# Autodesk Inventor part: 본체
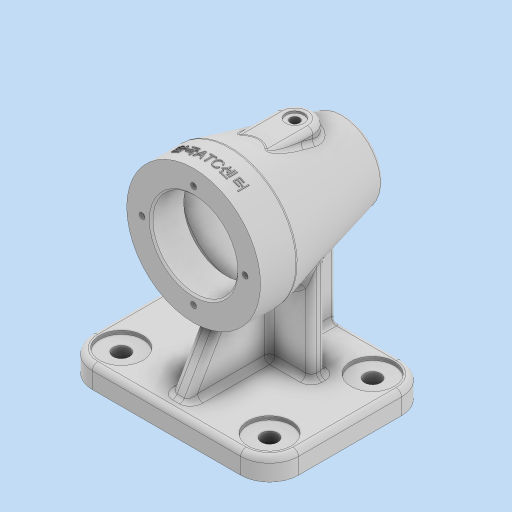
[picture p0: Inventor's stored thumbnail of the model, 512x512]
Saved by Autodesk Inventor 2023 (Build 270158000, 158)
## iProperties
Created: 2024-12
Part Number: 본체
Material: 일반
Document SubType Name: Modeling
Designer: asung
Density: 1 g/cm^3
Appearance: 기본값
Author: asung
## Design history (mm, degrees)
sketch "스케치1"
  geometry: L1 (41, -44.5)-(-41, -44.5); L2 (-57, -28.5)-(-57, 28.5); L3 (-41, 44.5)-(41, 44.5); L4 (57, 28.5)-(57, -28.5); L5 (57, -44.5)-(-57, 44.5); L6 (-57, -44.5)-(57, 44.5); A1 r 16 centre (41, -28.5) between (41, -44.5) and (57, -28.5); A2 r 16 centre (41, 28.5) between (57, 28.5) and (41, 44.5); A3 r 16 centre (-41, 28.5) between (-41, 44.5) and (-57, 28.5); A4 r 16 centre (-41, -28.5) between (-57, -28.5) and (-41, -44.5); 1 further point
  constraints: 12 end point, 8 point on circle, 8 point on line, 8 tangent, 4 centre point, 3 equal radius, 2 midpoint, 2 parallel, 1 horizontal, 1 perpendicular
  dimensions: "d0" = 114 distance of L5.end L6.end; "d1" = 89 distance of L6.start L5.end; "d2" = 16 radius of A1
extrude "돌출1" new body sketch "스케치1" distance "d3" = 12; taper "d4" = 0 deg
fillet "모깎기1" dims "d5" = 3
sketch "스케치2"
  geometry: A1 r 16 centre (-41, 28.5) between (-41, 44.5) and (-57, 28.5) reference; A2 r 16 centre (41, 28.5) between (57, 28.5) and (41, 44.5) reference; A3 r 16 centre (-41, -28.5) between (-57, -28.5) and (-41, -44.5) reference; A4 r 16 centre (41, -28.5) between (41, -44.5) and (57, -28.5) reference; 5 further points
  constraints: 4 coincident
hole "구멍1" sketch "스케치2" at (-41, 28.5), (41, 28.5), (-41, -28.5), (41, -28.5) diameter "d6" = 9; stored, may be unused: countersink angle "d10" = 90 deg, drill point angle "d12" = 0 deg; dims "d7" = 6, "d8" = 24, "d9" = 2, "d11" = 12
node "작업 평면1"
sketch "스케치3"
  geometry: L1 (9, -44.5)-(0, -44.5) reference; L2 (0, -44.5)-(0, 44.5) reference; L3 (0, 44.5)-(9, 44.5) reference; L4 (12, 41.5)-(12, -41.5) reference; L5 (9, -44.5)-(0, -44.5) reference; L6 (0, -44.5)-(0, 44.5) reference; L7 (0, 44.5)-(9, 44.5) reference; L8 (12, 41.5)-(12, -41.5) reference; L9 (9, -44.5)-(0, -44.5) reference; L10 (0, -44.5)-(0, 44.5) reference; L11 (0, 44.5)-(9, 44.5) reference; L12 (12, 41.5)-(12, -41.5) reference; L13 (0, 44.5)-(82, 44.5); L14 (82, 44.5)-(82, 29.5); L15 (82, 29.5)-(82, -54.5); L16 (119, 29.5)-(45, 29.5); L17 (103, -54.5)-(61, -54.5); L18 (119, 29.5)-(119, 9.5); L19 (119, 9.5)-(103, -54.5); A1 r 3 centre (9, -41.5) between (9, -44.5) and (12, -41.5) reference; A2 r 3 centre (9, 41.5) between (12, 41.5) and (9, 44.5) reference; A3 r 3 centre (9, -41.5) between (9, -44.5) and (12, -41.5) reference; A4 r 3 centre (9, 41.5) between (12, 41.5) and (9, 44.5) reference; A5 r 3 centre (9, -41.5) between (9, -44.5) and (12, -41.5) reference; A6 r 3 centre (9, 41.5) between (12, 41.5) and (9, 44.5) reference; 1 further point
  constraints: 14 end point, 3 horizontal, 2 midpoint, 2 vertical, 1 perpendicular
  dimensions: "d14" = 82 distance of L2.end L13.end; "d15" = 15 distance of L14.end L13.end; "d16" = 84 distance of L14.end L15.end; "d17" = 74 distance of L16.start L16.end; "d18" = 42 distance of L17.start L17.end; "d19" = 20 distance of L16.start L18.end
revolve "회전1" sketch "스케치3" stored, may be unused: angle "d20" = 90 deg
fillet "모깎기2" dims "d21" = 3
sketch "스케치4"
  geometry: L1 through (9, -44.5) direction (-1, 0) reference; L2 through (0, 44.5) direction (1, 9.87e-16) reference; L3 through (12, 41.5) direction (0, -1) reference; L4 through (100.658, -54.5) direction (-1, 0) reference; L5 through (60.432, -52.228) direction (-0.243, 0.97) reference; L6 through (45, 9.869) direction (0, 1) reference; L7 through (119, 29.5) direction (0, -1) reference; L8 through (9, -44.5) direction (-1, 0) reference; L9 through (0, 44.5) direction (1, 9.87e-16) reference; L10 through (12, 41.5) direction (0, -1) reference; L11 through (118.91, 9.142) direction (-0.243, -0.97) reference; L12 through (100.658, -54.5) direction (-1, 0) reference; L13 through (60.432, -52.228) direction (-0.243, 0.97) reference; L14 through (45, 9.869) direction (0, 1) reference; L15 through (45, 29.5) direction (1, 2.4e-16) reference; L16 through (119, 29.5) direction (0, -1) reference; L17 through (9, -44.5) direction (-1, 0) reference; L18 through (0, 44.5) direction (1, 9.87e-16) reference; L19 through (12, 41.5) direction (0, -1) reference; L20 through (118.91, 9.142) direction (-0.243, -0.97) reference; L21 through (100.658, -54.5) direction (-1, 0) reference; L22 through (60.432, -52.228) direction (-0.243, 0.97) reference; L23 through (45, 9.869) direction (0, 1) reference; L24 through (45, 29.5) direction (1, 2.4e-16) reference; L25 through (119, 29.5) direction (0, -1) reference; L26 through (9, -44.5) direction (-1, 0) reference; L27 through (0, 44.5) direction (1, 9.87e-16) reference; L28 through (12, 41.5) direction (0, -1) reference; L29 through (118.91, 9.142) direction (-0.243, -0.97) reference; L30 through (100.658, -54.5) direction (-1, 0) reference; L31 through (60.432, -52.228) direction (-0.243, 0.97) reference; L32 through (45, 9.869) direction (0, 1) reference; L33 through (45, 29.5) direction (1, 2.4e-16) reference; L34 through (119, 29.5) direction (0, -1) reference; L35 through (9, -44.5) direction (-1, 0) reference; L36 through (0, 44.5) direction (1, 9.87e-16) reference; L37 through (12, 41.5) direction (0, -1) reference; L38 through (118.91, 9.142) direction (-0.243, -0.97) reference; L39 through (100.658, -54.5) direction (-1, 0) reference; L40 through (60.432, -52.228) direction (-0.243, 0.97) reference; L41 through (45, 9.869) direction (0, 1) reference; L42 through (45, 29.5) direction (1, 2.4e-16) reference; L43 through (119, 29.5) direction (0, -1) reference; L44 through (9, -44.5) direction (-1, 0) reference; L45 through (0, 44.5) direction (1, 9.87e-16) reference; L46 through (12, 41.5) direction (0, -1) reference; L47 through (118.91, 9.142) direction (-0.243, -0.97) reference; L48 through (60.432, -52.228) direction (-0.243, 0.97) reference; L49 through (45, 9.869) direction (0, 1) reference; L50 through (45, 29.5) direction (1, 2.4e-16) reference; L51 (82, 29.5)-(82, -54.5); L52 (105.5, 29.5)-(105.5, 11.5); L53 (105.5, 11.5)-(107.942, 11.5); L54 (112.793, 5.287)-(103.664, -31.228); L55 (100.754, -33.5)-(99.5, -33.5); L56 (99.5, -33.5)-(99.5, -43.2); L57 (99.2, -43.5)-(97.5, -43.5); L58 (95.914, -43.5)-(95.914, -43.5); L59 (94.5, -46.5)-(82, -46.5); L60 (97.5, -43.5)-(97.5, -43.5); L61 through (9, -44.5) direction (-1, 0) reference; L62 through (0, 44.5) direction (1, 9.87e-16) reference; L63 through (12, 41.5) direction (0, -1) reference; L64 through (118.91, 9.142) direction (-0.243, -0.97) reference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; A1 r 5 centre (107.942, 6.5) between (112.793, 5.287) and (107.942, 11.5); A2 r 3 centre (100.754, -30.5) between (100.754, -33.5) and (103.664, -31.228); A3 r 0.3 centre (99.2, -43.2) between (99.2, -43.5) and (99.5, -43.2); A4 r 3 centre (94.5, -43.5) between (94.5, -46.5) and (97.5, -43.5); 83 further points; 32 other entities
  constraints: 20 end point, 9 point on line, 8 horizontal alignment, 8 point on circle, 8 tangent, 6 perpendicular, 4 centre point, 1 horizontal, 1 vertical, 121 other
  dimensions: "d22" = 5 dimension on L54; "d23" = 47 diameter of L52 L51; "d24" = 18 dimension on L53; "d25" = 45 vertical distance of point (114.346, 11.5) point (103.096, -33.5); "d26" = 10 distance of L55.end point (99.5, -43.5); "d28" = 5 radius of A1; "d29" = 3 radius of A2; "d30" = 0.3 radius of A3; "d31" = 35 diameter of L56 L51; "d33" = 31 diameter of L60 L51; "d34" = 3 distance between parallel lines of L57 L59; "d35" = 3 radius of A4 (derived)
  node "절단 모서리 투영4"
  node "절단 모서리 투영5"
  node "절단 모서리 투영6"
  node "절단 모서리 투영7"
  node "절단 모서리 투영8"
  node "절단 모서리 투영9"
  node "절단 모서리 투영10"
  node "절단 모서리 투영11"
  node "절단 모서리 투영12"
  node "절단 모서리 투영13"
  node "절단 모서리 투영14"
  node "절단 모서리 투영15"
  node "절단 모서리 투영16"
revolve "회전2" stored, may be unused: angle "d37" = 90 deg
chamfer "모따기1" distance "d38" = 1; stored, may be unused: second distance "d39" = 2, angle "d40" = 45 deg
chamfer "모따기2" distance "d41" = 1; stored, may be unused: second distance "d42" = 2, angle "d43" = 45 deg
node "작업 평면2"
sketch "스케치5"
  geometry: L1 (24.5, 29.5)-(-24.5, 29.5) reference; L2 (0, 29.5)-(0, -26.5); L3 (10, 29.5)-(10, -26.5); L4 (-10, 29.5)-(-10, -26.5); L5 (-16.733, 9.869)-(-16.733, 29.5) reference; L6 (-16.733, 29.5)-(16.733, 29.5) reference; L7 (16.733, 29.5)-(16.733, 9.869) reference; L8 (-10, 29.5)-(10, 29.5); L9 (-16.733, 9.869)-(-16.733, 29.5) reference; L10 (-16.733, 29.5)-(16.733, 29.5) reference; L11 (16.733, 29.5)-(16.733, 9.869) reference; L12 (-16.733, 9.869)-(-16.733, 29.5) reference; L13 (-16.733, 29.5)-(16.733, 29.5) reference; L14 (16.733, 29.5)-(16.733, 9.869) reference; L15 (-21.568, -52.228)-(21.568, -52.228) reference; L16 (36.91, 9.142)-(-36.91, 9.142) reference; L17 (30.793, 5.287)-(-30.793, 5.287) reference; C1 r 10 at (0, -26.5); 5 further points
  constraints: 8 end point, 3 horizontal alignment, 2 parallel, 1 centre point, 1 coincident, 1 collinear, 1 midpoint, 1 vertical, 6 other
  dimensions: "d45" = 56 distance of L2.start L2.end; "d46" = 20 diameter of C1; "d47" = 10 distance between parallel lines of L2 L3; "d48" = 10 distance between parallel lines of L2 L4; "d49" = 0 distance between parallel lines of L8 L1; "d50" = 56 distance from line of L3.end L1; "d51" = 56 distance from line of L4.end L1
extrude "돌출2" join sketch "스케치5" distance "d52" = 8; taper "d53" = 0 deg
revolve "회전3" stored, may be unused: angle "d55" = 90 deg
sketch "스케치6"
  geometry: A1 r 10 centre (0, 26.5) between (10, 26.5) and (-10, 26.5) reference; 2 further points
  constraints: 1 coincident
hole "구멍2" sketch "스케치6" at (0, 26.5) diameter "d56" = 5.1881; stored, may be unused: countersink angle "d60" = 90 deg, drill point angle "d62" = 118 deg; dims "d57" = 20, "d58" = 10, "d59" = 1, "d61" = 20
fillet "모깎기3" dims "d63" = 3
fillet "모깎기4" dims "d64" = 3
sketch "스케치7"
  geometry: L1 (-28, 15.5)-(28, 15.5); L2 (28, 15.5)-(28, 7.5); L3 (28, 7.5)-(-28, 7.5); L4 (-28, 7.5)-(-28, 15.5); L5 (41, 44.5)-(-41, 44.5) reference; L6 (0, 44.5)-(0, 15.5); 1 further point
  constraints: 10 end point, 2 midpoint, 2 parallel, 1 horizontal, 1 perpendicular, 1 vertical
  dimensions: "d65" = 56 distance of L2.end L3.end; "d66" = 8 distance of L1.end L2.end; "d67" = 29 distance of L6.end L6.start
extrude "돌출3" join sketch "스케치7" stored distance "d68" = 8; taper "d69" = 0 deg
sketch "스케치8"
  geometry: L1 (105.5, 28.5)-(106.5, 29.5) reference; L2 (106.5, 29.5)-(119, 29.5) reference; L3 (119, 29.5)-(119, 9.869) reference; L4 (118.91, 9.142)-(115.09, -6.142) reference; L5 (115, -6.869)-(115, -21.5) reference; L6 (115, -21.5)-(114, -21.5) reference; L7 (114, -21.5)-(114, -23.906) reference; L8 (114, -23.906)-(105.495, -23.906) reference; L9 (105.495, -23.906)-(112.793, 5.287) reference; L10 (107.942, 11.5)-(105.5, 11.5) reference; L11 (105.5, 11.5)-(105.5, 28.5) reference; L12 (69.5, -46.5)-(94.5, -46.5) reference; L13 (97.5, -43.5)-(99.2, -43.5) reference; L14 (99.5, -43.2)-(99.5, -34.5) reference; L15 (99.5, -34.5)-(100.5, -33.5) reference; L16 (100.5, -33.5)-(100.754, -33.5) reference; L17 (103.664, -31.228)-(104.198, -29.094) reference; L18 (104.198, -29.094)-(114, -29.094) reference; L19 (114, -29.094)-(114, -31.5) reference; L20 (114, -31.5)-(115, -31.5) reference; L21 (115, -31.5)-(115, -33.5) reference; L22 (112, -36.5)-(109.842, -36.5) reference; L23 (106.932, -38.772)-(103.568, -52.228) reference; L24 (100.658, -54.5)-(63.342, -54.5) reference; L25 (60.432, -52.228)-(51.25, -15.5) reference; L26 (51.25, -15.5)-(12, -15.5) reference; L27 (12, -15.5)-(12, -41.5) reference; L28 (9, -44.5)-(0, -44.5) reference; L29 (0, -44.5)-(0, 44.5) reference; L30 (0, 44.5)-(9, 44.5) reference; L31 (12, 41.5)-(12, -7.5) reference; L32 (12, -7.5)-(49.25, -7.5) reference; L33 (49.25, -7.5)-(45.09, 9.142) reference; L34 (45, 9.869)-(45, 29.5) reference; L35 (45, 29.5)-(57.5, 29.5) reference; L36 (57.5, 29.5)-(58.5, 28.5) reference; L37 (58.5, 28.5)-(58.5, 11.5) reference; L38 (58.5, 11.5)-(56.058, 11.5) reference; L39 (51.207, 5.287)-(60.336, -31.228) reference; L40 (63.246, -33.5)-(63.5, -33.5) reference; L41 (63.5, -33.5)-(64.5, -34.5) reference; L42 (64.5, -34.5)-(64.5, -43.2) reference; L43 (64.8, -43.5)-(66.5, -43.5) reference; L44 (105.5, 28.5)-(106.5, 29.5) reference; L45 (106.5, 29.5)-(119, 29.5) reference; L46 (119, 29.5)-(119, 9.869) reference; L47 (118.91, 9.142)-(115.09, -6.142) reference; L48 (115, -6.869)-(115, -21.5) reference; L49 (115, -21.5)-(114, -21.5) reference; L50 (114, -21.5)-(114, -23.906) reference; L51 (114, -23.906)-(105.495, -23.906) reference; L52 (105.495, -23.906)-(112.793, 5.287) reference; L53 (107.942, 11.5)-(105.5, 11.5) reference; L54 (105.5, 11.5)-(105.5, 28.5) reference; L55 (69.5, -46.5)-(94.5, -46.5) reference; L56 (97.5, -43.5)-(99.2, -43.5) reference; L57 (99.5, -43.2)-(99.5, -34.5) reference; L58 (99.5, -34.5)-(100.5, -33.5) reference; L59 (100.5, -33.5)-(100.754, -33.5) reference; L60 (103.664, -31.228)-(104.198, -29.094) reference; L61 (104.198, -29.094)-(114, -29.094) reference; L62 (114, -29.094)-(114, -31.5) reference; L63 (114, -31.5)-(115, -31.5) reference; L64 (115, -31.5)-(115, -33.5) reference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; A1 r 3 centre (116, 9.869) between (118.91, 9.142) and (119, 9.869) reference; A2 r 5 centre (107.942, 6.5) between (112.793, 5.287) and (107.942, 11.5) reference; A3 r 3 centre (94.5, -43.5) between (94.5, -46.5) and (97.5, -43.5) reference; A4 r 0.3 centre (99.2, -43.2) between (99.2, -43.5) and (99.5, -43.2) reference; A5 r 3 centre (100.754, -30.5) between (100.754, -33.5) and (103.664, -31.228) reference; A6 r 3 centre (112, -33.5) between (112, -36.5) and (115, -33.5) reference; A7 r 3 centre (100.658, -51.5) between (100.658, -54.5) and (103.568, -52.228) reference; A8 r 3 centre (63.342, -51.5) between (60.432, -52.228) and (63.342, -54.5) reference; A9 r 3 centre (9, -41.5) between (9, -44.5) and (12, -41.5) reference; A10 r 3 centre (9, 41.5) between (12, 41.5) and (9, 44.5) reference; A11 r 3 centre (48, 9.869) between (45, 9.869) and (45.09, 9.142) reference; A12 r 5 centre (56.058, 6.5) between (56.058, 11.5) and (51.207, 5.287) reference; A13 r 3 centre (63.246, -30.5) between (60.336, -31.228) and (63.246, -33.5) reference; A14 r 0.3 centre (64.8, -43.2) between (64.5, -43.2) and (64.8, -43.5) reference; A15 r 3 centre (69.5, -43.5) between (66.5, -43.5) and (69.5, -46.5) reference; A16 r 3 centre (116, 9.869) between (118.91, 9.142) and (119, 9.869) reference; A17 r 5 centre (107.942, 6.5) between (112.793, 5.287) and (107.942, 11.5) reference; A18 r 3 centre (94.5, -43.5) between (94.5, -46.5) and (97.5, -43.5) reference; A19 r 0.3 centre (99.2, -43.2) between (99.2, -43.5) and (99.5, -43.2) reference; A20 r 3 centre (100.754, -30.5) between (100.754, -33.5) and (103.664, -31.228) reference; A21 r 3 centre (112, -33.5) between (112, -36.5) and (115, -33.5) reference; A22 r 3 centre (100.658, -51.5) between (100.658, -54.5) and (103.568, -52.228) reference; A23 r 3 centre (63.342, -51.5) between (60.432, -52.228) and (63.342, -54.5) reference; A24 r 3 centre (9, -41.5) between (9, -44.5) and (12, -41.5) reference; A25 r 3 centre (9, 41.5) between (12, 41.5) and (9, 44.5) reference; A26 r 3 centre (48, 9.869) between (45, 9.869) and (45.09, 9.142) reference; A27 r 5 centre (56.058, 6.5) between (56.058, 11.5) and (51.207, 5.287) reference; A28 r 3 centre (63.246, -30.5) between (60.336, -31.228) and (63.246, -33.5) reference; A29 r 0.3 centre (64.8, -43.2) between (64.5, -43.2) and (64.8, -43.5) reference; A30 r 3 centre (69.5, -43.5) between (66.5, -43.5) and (69.5, -46.5) reference; A31 r 3 centre (116, 9.869) between (118.91, 9.142) and (119, 9.869) reference; A32 r 5 centre (107.942, 6.5) between (112.793, 5.287) and (107.942, 11.5) reference; A33 r 3 centre (94.5, -43.5) between (94.5, -46.5) and (97.5, -43.5) reference; A34 r 0.3 centre (99.2, -43.2) between (99.2, -43.5) and (99.5, -43.2) reference; A35 r 3 centre (100.754, -30.5) between (100.754, -33.5) and (103.664, -31.228) reference; A36 r 3 centre (112, -33.5) between (112, -36.5) and (115, -33.5) reference; A37 r 3 centre (100.658, -51.5) between (100.658, -54.5) and (103.568, -52.228) reference; A38 r 3 centre (63.342, -51.5) between (60.432, -52.228) and (63.342, -54.5) reference; A39 r 3 centre (9, -41.5) between (9, -44.5) and (12, -41.5) reference; A40 r 3 centre (9, 41.5) between (12, 41.5) and (9, 44.5) reference; A41 r 3 centre (48, 9.869) between (45, 9.869) and (45.09, 9.142) reference; A42 r 5 centre (56.058, 6.5) between (56.058, 11.5) and (51.207, 5.287) reference; A43 r 3 centre (63.246, -30.5) between (60.336, -31.228) and (63.246, -33.5) reference; A44 r 0.3 centre (64.8, -43.2) between (64.5, -43.2) and (64.8, -43.5) reference; A45 r 3 centre (69.5, -43.5) between (66.5, -43.5) and (69.5, -46.5) reference; 1 further point
  constraints: 4 end point, 3 point on line, 1 horizontal, 6 other
  dimensions: "d70" = 7 distance from line of L30 L132.end; "d71" = 60 deg angle of L31 L132
  node "절단 모서리 투영20"
  node "절단 모서리 투영21"
  node "절단 모서리 투영22"
feature "리브1" dims "d72" = 1, "d73" = 10, "d74" = 0, "d75" = 0, "d76" = 1, "d77" = 1
feature "리브2" dims "d78" = 1, "d79" = 10, "d80" = 0, "d81" = 0, "d82" = 1, "d83" = 1
fillet "모깎기5" dims "d84" = 3
fillet "모깎기6" dims "d85" = 3
sketch "스케치9"
  geometry: L1 (-52.958, -72)-(-45.387, -72) reference; L2 (-45.387, -72)-(-45.387, -82) reference; L3 (-45.387, -82)-(-56.969, -82) reference; L4 (-56.969, -82)-(-56.969, -73) reference; L5 (-53.961, -70)-(-52.958, -70) reference; L6 (-52.958, -70)-(-52.958, -72) reference; L7 (29.042, -72)-(36.613, -72) reference; L8 (36.613, -72)-(36.613, -82) reference; L9 (36.613, -82)-(-36.613, -82) reference; L10 (-36.613, -82)-(-36.613, -72) reference; L11 (-36.613, -72)-(-29.042, -72) reference; L12 (-29.042, -72)-(-29.042, -70) reference; L13 (-29.042, -70)-(-8, -70) reference; L14 (-5, -67)-(-5, -62.144) reference; L15 (-2, -56.144)-(2, -56.144) reference; L16 (5, -62.144)-(5, -67) reference; L17 (8, -70)-(29.042, -70) reference; L18 (29.042, -70)-(29.042, -72) reference; L19 (45.387, -72)-(52.958, -72) reference; L20 (52.958, -72)-(52.958, -70) reference; L21 (52.958, -70)-(53.961, -70) reference; L22 (56.969, -73)-(56.969, -82) reference; L23 (56.969, -82)-(45.387, -82) reference; L24 (45.387, -82)-(45.387, -72) reference; C1 r 37 at (0, 0) reference; C2 r 37 at (0, 0) reference; C3 r 24.5 at (0, 0) reference; A1 r 3 centre (-8, -67) between (-8, -70) and (-5, -67) reference; A2 r 3 centre (8, -67) between (5, -67) and (8, -70) reference; A3 r 28.5 centre (0, 0) between (0, 28.5) and (-28.5, 0); 5 further points; 2 other entities
  constraints: 4 point on circle, 2 horizontal alignment, 2 vertical alignment, 1 centre point, 1 coincident, 4 other
  dimensions: "d86" = 57 diameter of A3
  node "절단 모서리 투영23"
node "작업 평면3"
sketch "스케치10"
  geometry: L1 (-37, 10)-(37, 10) reference; 2 further points
  constraints: 1 vertical alignment, 1 other
  dimensions: "d87" = 9 distance from line of L1 point (0, 1)
feature "엠보싱1" sketch "스케치10" dims "d0" = 114, "d1" = 89, "d2" = 16, "d88" = 0.5, "d89" = 0
hole "구멍3" sketch "스케치9" diameter "d90" = 3.242; stored, may be unused: countersink angle "d94" = 90 deg, drill point angle "d96" = 118 deg; dims "d91" = 8, "d92" = 4, "d93" = 2, "d95" = 10
feature "ڪ耀ڬ耀ڮ耀ڰ耀ڲ耀ڴ耀ڶ耀ڸ耀" dims "d0" = 114, "d1" = 89, "d2" = 16, "d3" = 12, "d4" = 0, "d5" = 3, "d6" = 9, "d7" = 6, "d8" = 24, "d9" = 2, "d10" = 90 deg, "d11" = 12, "d12" = 0, "d13" = -15, "d14" = 82, "d15" = 15, "d16" = 84, "d17" = 74, "d18" = 42, "d19" = 20, "d20" = 90 deg, "d21" = 3, "d22" = 5, "d23" = 47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
node "솔리드1"
node "투영된 루프1"
node "절단 모서리 투영1"
node "절단 모서리 투영2"
node "절단 모서리 투영3"
node "절단 모서리 투영17"
node "절단 모서리 투영18"
node "절단 모서리 투영19"
feature "A9D066F2-1C7D-4E18-AEED-F7BC21143FA4" dims "d6" = 9, "d7" = 6, "d8" = 24, "d9" = 2, "d10" = 90 deg, "d11" = 12, "d12" = 0
